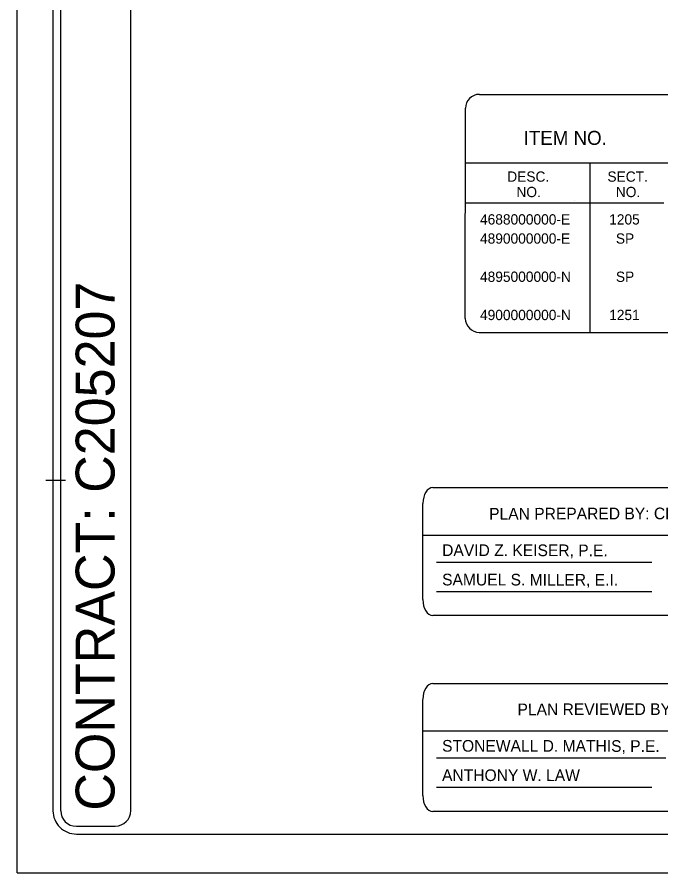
# Model space of a CAD drawing. Extents: x -63 to 3072, y 0 to 1100.
# Drawn here: x 0 to 414, y 0 to 550 of the extents above; entities that cross this region are included whole.
import ezdxf

# ---------------------------------------------------------------- set-up
doc = ezdxf.new("R2010")
doc.units = 0
for name, color, linetype in [('Default', 7, 'Continuous'), ('Scratch_Level_0', 7, 'Continuous'), ('Sheet Data Text CELL', 7, 'Continuous'), ('Sheet_Data_Field_CELL', 7, 'Continuous'), ('Sheet_RDY_PE_Seal_Cell', 7, 'Continuous')]:
    doc.layers.add(name, color=color, linetype=linetype)

msp = doc.modelspace()

# ---------------------------------------------------------------- linework, layer by layer
at = {"layer": 'Default'}
msp.add_line((358.1, 431.82), (358.1, 431.82), dxfattribs=at)
at = {"layer": 'Scratch_Level_0'}
for q in [(0, 1100), (1699.98, 0)]:
    msp.add_line((0, 0), q, dxfattribs=at)
at = {"layer": 'Sheet_Data_Field_CELL'}
msp.add_line((0, 0), (0, 0), dxfattribs=at)
at = {"layer": 'Sheet_RDY_PE_Seal_Cell'}
for p, q in [((23.05, 1059.92), (23.05, 39.96)), ((28.05, 39.96), (28.05, 1059.92)), ((73.05, 39.99), (73.05, 1059.99)), ((297.1, 500.34), (451.56, 500.25)), ((288.09, 356.3), (288.18, 491.43)), ((288.17, 456.28), (774.84, 456.28)), ((368.39, 347.36), (368.39, 456.27)), ((288.16, 430.7), (415.72, 430.7)), ((297, 347.39), (848.65, 347.17)), ((18.5, 252.49), (31, 252.5)), ((18.5, 252.49), (31, 252.5)), ((267.24, 247.66), (765.08, 247.66)), ((260.8, 175.66), (260.82, 237.47)), ((260.8, 217.06), (558.94, 217)), ((269.57, 199.77), (408.01, 199.77)), ((269.55, 180.89), (408.01, 180.89)), ((765.05, 165.37), (267.21, 165.37)), ((267.21, 121.74), (710, 121.74)), ((260.77, 49.7), (260.79, 111.54)), ((260.78, 91.25), (716.4, 91.25)), ((269.54, 74.05), (416.87, 74.05)), ((269.52, 55.18), (407.93, 55.18)), ((709.97, 39.46), (267.18, 39.46)), ((38.07, 29.94), (63.03, 29.94)), ((38.07, 24.99), (1652, 24.99))]:
    msp.add_line(p, q, dxfattribs=at)
for centre, radius, start, end in [((297.09, 491.43), 8.91, 89.9734, 179.9734), ((297, 356.3), 8.91, 179.9734, 269.9734), ((38.05, 39.99), 15, 180.0932, 270.0932), ((38.07, 39.96), 10.02, 180, 270), ((63.05, 39.99), 10, 270, 360)]:
    msp.add_arc(centre, radius, start, end, dxfattribs=at)
for centre, major_axis, start_param, end_param in [((267.24, 237.47), (0.01, 10.24), 0.000702, 1.571498), ((267.22, 175.66), (-0.01, -10.24), 4.713091, 6.283887), ((267.21, 111.51), (0.01, 10.24), 0.000687, 1.567869), ((267.19, 49.7), (-0.01, -10.24), 4.713091, 6.283872)]:
    msp.add_ellipse(centre, major_axis=major_axis, ratio=0.62659, start_param=start_param, end_param=end_param, dxfattribs=at)

# ---------------------------------------------------------------- texts
at = {"layer": 'Sheet Data Text CELL'}
for s, p in [('PLAN PREPARED BY: CDM SMITH, INC.', (303.4, 227.05)), ('PLAN REVIEWED BY: N.C.D.O.T. DIVISION 3', (321.62, 101.32))]:
    msp.add_text(s, height=7.5, rotation=0.1194, dxfattribs=at).set_placement(p)
at = {"layer": 'Sheet_Data_Field_CELL'}
for s, height, p in [('ITEM NO.', 9, (325.56, 467.89)), ('DESC.', 6.6, (315.05, 444.21)), ('SECT.', 6.6, (379.43, 444.21)), ('NO.', 6.6, (320.94, 434.31)), ('NO.', 6.6, (384.81, 434.31)), ('4688000000-E', 6.6, (297.53, 416.7)), ('1205', 6.6, (380.55, 416.69)), ('4890000000-E', 6.6, (297.53, 404.41)), ('SP', 6.6, (384.87, 404.41)), ('4895000000-N', 6.6, (297.53, 379.85)), ('SP', 6.6, (384.87, 379.84)), ('4900000000-N', 6.6, (297.53, 355.28)), ('1251', 6.6, (380.55, 355.28))]:
    msp.add_text(s, height=height, dxfattribs=at).set_placement(p)
for s, p in [('DAVID Z. KEISER, P.E.', (273.18, 203.64)), ('SAMUEL S. MILLER, E.I.', (273.16, 184.76)), ('STONEWALL D. MATHIS, P.E.', (273.14, 77.92)), ('ANTHONY W. LAW', (273.13, 59.05))]:
    msp.add_text(s, height=7.5, rotation=359.9372, dxfattribs=at).set_placement(p)
at = {"layer": 'Sheet_RDY_PE_Seal_Cell'}
msp.add_text('CONTRACT: C205207', height=25, rotation=90, dxfattribs=at).set_placement((62.63, 39.99))

doc.saveas('drawing.dxf')
